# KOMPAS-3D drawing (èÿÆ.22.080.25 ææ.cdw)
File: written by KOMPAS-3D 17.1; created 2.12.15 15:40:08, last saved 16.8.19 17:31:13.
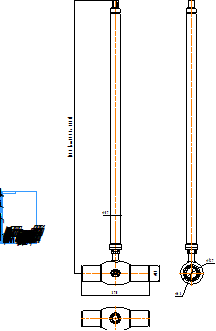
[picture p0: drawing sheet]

Sheet 1: A4, portrait

Title block, sheet 1: name: КШТ.22.080.25 С/С; sheets: 1; organisation: ООО "АДЛ Групп"; sheet format: A4; stored path: C:\Users\kka\KOMPAS_Work\Модели кранов для исследований\DN50\С удлинением\КШГ.32.050.40 СС ГЧ _ Шаровой кран БИВАЛ Ду50 Ру4 МПа редуцированный под приварку, с удлинением штока H=1100.cdw

Views: Вид 1, Проекционный вид 2, Проекционный вид 3
Referenced files in C:\Users\kka\KOMPAS_Work\Модели кранов для исследований\DN80\С удлинением\: КШТ.22.080.25 СС.a3d, КШГ.35.065.25 СС.a3d!КШГ.45.065.10 СС!Деталь (локальная).m3d
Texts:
  Klimkovich
  ADL
  (от 297 до 5000)
  Рама для чертежей
  Лит-Масса-Масштаб
  Материал-Предприятие
  Масштаб
  Изм.
  Лист
  № докум.
  Подп.
  Дата
  Лит.
  Разраб.
  Пров.
  Т.контр.
  Листов
  Внимание! Данный продукт является объектом авторского права ООО «Торговый Дом АДЛ».
  Запрещается изменение, копирование, распространение
  (в том числе путем копирования на другие сайты и ресурсы в Интернете)
  или любое иное использование информации и объектов без предварительного
  согласия правообладателя (ООО «Торговый Дом АДЛ»).
  Н.контр.
  Утв.
  ООО "Торговый дом АДЛ"
  Изменение
  Номер документа
  Подпись
  Обозначение документа
  Наименование изделия
  Масса изделия по ГОСТ 2.109-73
  Порядковый номер листа
  Общее количество листов в документе
  Характер работы, выполненной лицом, подписавшим документ
  Наименование или индекс предприятия, выпускающего документ
  Инв. № подл.
  Подп. и дата
  Взам. инв. №
  Инв. № дубл.
  Инвентарный номер подлинника по ГОСТ 2.501-68
  Подпись принявшего подлинник в отдел технической документации
  Инвентарный номер подлинника, взамен которого выпущен данный подлинник
  Инвентарный номер дубликата по ГОСТ 2.502-68
  Подпись принявшего дубликат в отдел технической документации
  Справ. №
  Перв. примен.
  Обозначение документа, взамен или на основании которого выпущен данный документ
  Обозначение документа, в котором впервые записан данный документ
  Подпись лица, копировавшего чертеж
  Обозначение формата листа
  !Рама для чертежа
Dimensions and other numbers on the sheet: 1500; 57; 370; 89; 63; 127; 1:1; 1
